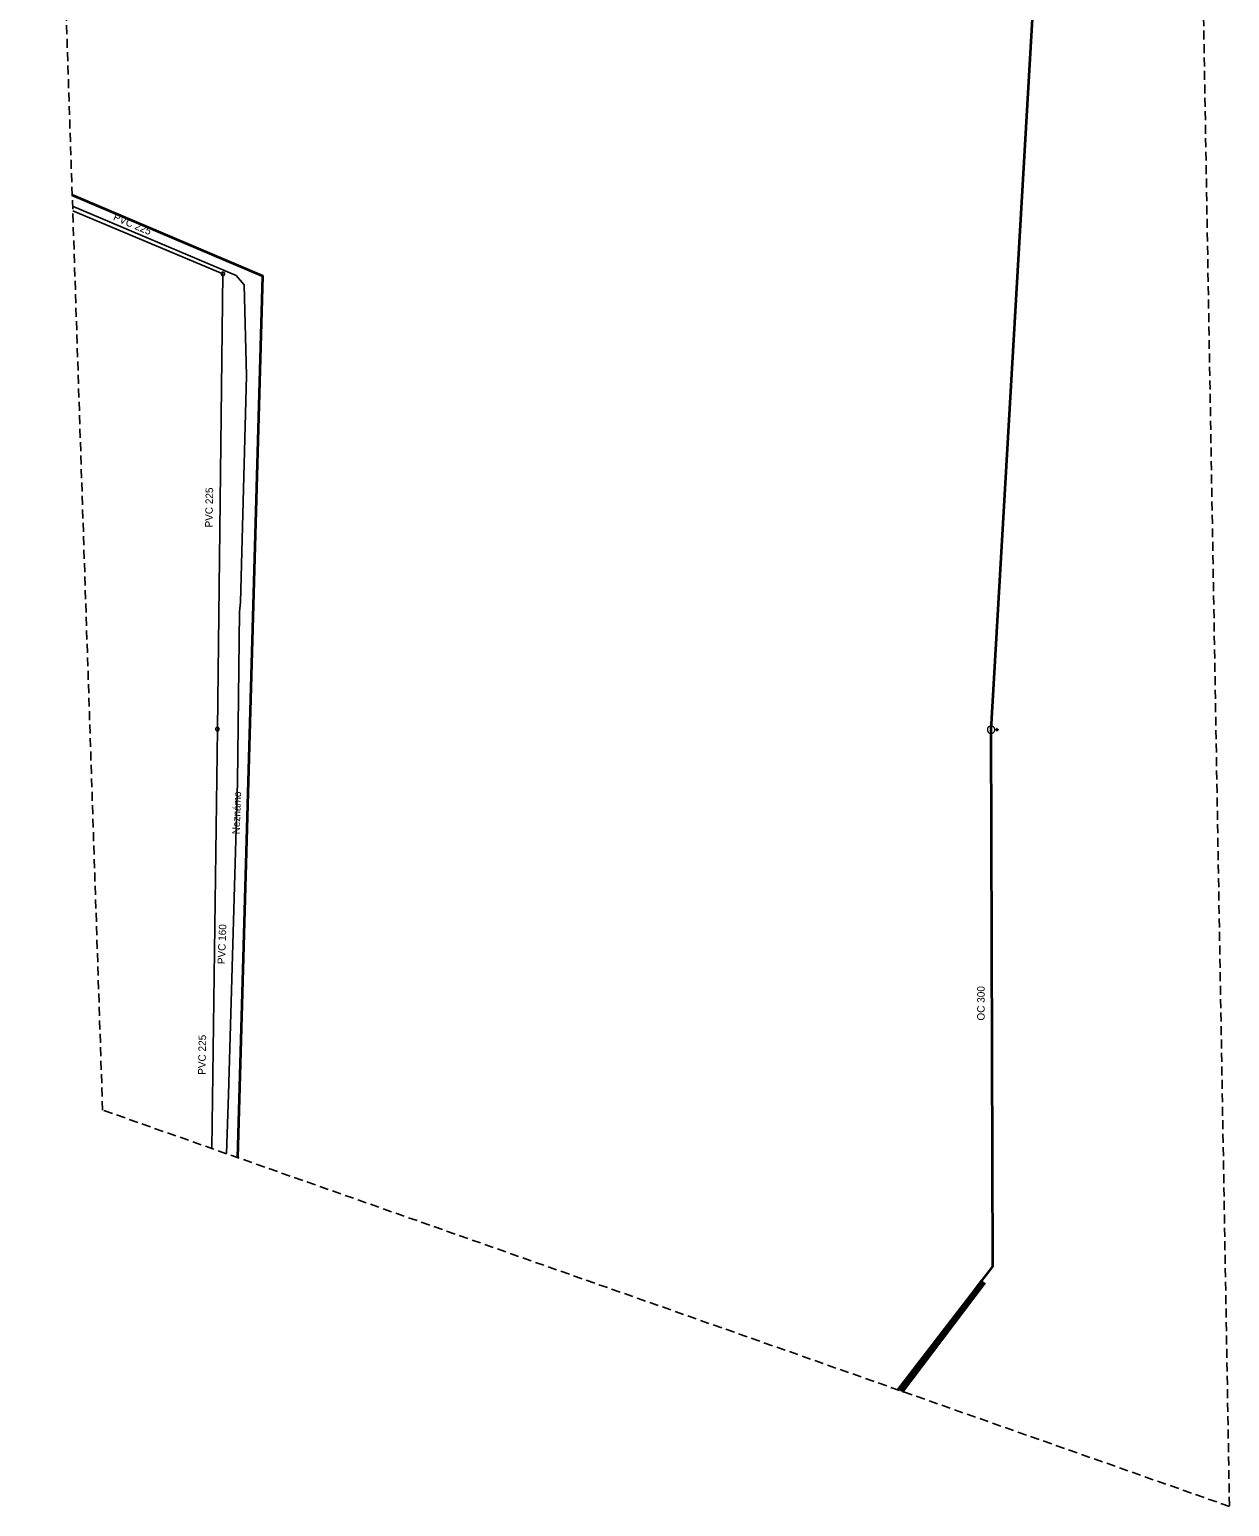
# Model space of a CAD drawing. Extents: x -724334 to -723692, y -972150 to -970648.
# Drawn here: x -723852.3 to -723691.8, y -972150.1 to -971952.5 of the extents above; entities that cross this region are included whole.
import ezdxf

# ---------------------------------------------------------------- set-up
doc = ezdxf.new("R2010")
doc.units = 0
doc.header["$LTSCALE"] = 0.4
doc.linetypes.add('MEDIUM_DASHED', pattern=[4.5, 3, -1.5])
for name, color, linetype, lineweight in [('1', 7, 'Continuous', 25), ('11', 7, 'Continuous', 13), ('17', 7, 'Continuous', 35), ('23', 7, 'Continuous', 13), ('3', 7, 'Continuous', 106)]:
    doc.layers.add(name, color=color, linetype=linetype, lineweight=lineweight)

msp = doc.modelspace()

# ---------------------------------------------------------------- linework, layer by layer
at = {"layer": '1', "linetype": 'MEDIUM_DASHED'}
msp.add_lwpolyline([(-723848.074, -970648.428), (-723714.095, -970720.999), (-724065.788, -971064.318), (-723792.249, -971201.088), (-723702.93, -971508.122), (-723691.766, -972150.101), (-723842.491, -972097.068), (-723864.821, -971424.385), (-723982.052, -971259.703), (-724333.745, -971117.352)], close=True, dxfattribs=at)
at = {"layer": '11', "lineweight": 35}
msp.add_lwpolyline([(-723824.393, -972103.436), (-723821.07, -971985.522), (-723846.553, -971974.691)], dxfattribs=at)
at = {"layer": '17', "lineweight": 25}
for p, q in [((-723846.484, -971976.784), (-723826.388, -971985.208)), ((-723826.388, -971985.208), (-723827.138, -972046.099)), ((-723827.138, -972046.099), (-723827.873, -972102.211))]:
    msp.add_line(p, q, dxfattribs=at)
at = {"layer": '17'}
msp.add_lwpolyline([(-723736.101, -972134.501), (-723723.419, -972117.993), (-723723.649, -972046.19), (-723706.064, -971743.847)], dxfattribs=at)
at = {"layer": '17', "lineweight": 25}
msp.add_lwpolyline([(-723846.505, -971976.143), (-723824.629, -971985.42), (-723823.55, -971986.68), (-723823.239, -971998.829), (-723824.05, -972029.1), (-723824.19, -972030.42), (-723824.44, -972053.219), (-723825.629, -972094.98), (-723825.929, -972102.895)], dxfattribs=at)
at = {"layer": '23'}
for p, q in [((-723826.345, -971984.959), (-723826.433, -971985.466)), ((-723827.095, -972045.85), (-723827.183, -972046.357)), ((-723722.692, -972046.18), (-723723.157, -972046.182)), ((-723722.94, -972046.017), (-723722.94, -972046.182)), ((-723722.938, -972046.347), (-723722.692, -972046.18)), ((-723722.917, -972046.031), (-723722.916, -972046.331)), ((-723722.889, -972046.048), (-723722.888, -972046.315)), ((-723722.866, -972046.066), (-723722.864, -972046.294)), ((-723722.843, -972046.083), (-723722.84, -972046.279)), ((-723722.818, -972046.098), (-723722.816, -972046.264)), ((-723722.791, -972046.114), (-723722.79, -972046.248)), ((-723722.767, -972046.13), (-723722.765, -972046.231)), ((-723722.743, -972046.149), (-723722.742, -972046.213)), ((-723722.716, -972046.164), (-723722.715, -972046.196))]:
    msp.add_line(p, q, dxfattribs=at)
for points in [[(-723826.14, -971985.253), (-723826.137, -971985.226), (-723826.136, -971985.2), (-723826.138, -971985.174), (-723826.143, -971985.149), (-723826.15, -971985.122), (-723826.161, -971985.098), (-723826.174, -971985.074), (-723826.188, -971985.054), (-723826.205, -971985.033), (-723826.225, -971985.016), (-723826.246, -971985), (-723826.268, -971984.986), (-723826.293, -971984.974), (-723826.318, -971984.967), (-723826.343, -971984.961), (-723826.369, -971984.958), (-723826.396, -971984.956), (-723826.422, -971984.958), (-723826.448, -971984.963), (-723826.473, -971984.97), (-723826.497, -971984.981), (-723826.52, -971984.994), (-723826.542, -971985.008), (-723826.561, -971985.026), (-723826.579, -971985.045), (-723826.596, -971985.067), (-723826.61, -971985.088), (-723826.621, -971985.113), (-723826.63, -971985.138), (-723826.635, -971985.163), (-723826.639, -971985.189), (-723826.64, -971985.215), (-723826.638, -971985.242), (-723826.632, -971985.268), (-723826.624, -971985.294), (-723826.614, -971985.317), (-723826.601, -971985.341), (-723826.588, -971985.362), (-723826.57, -971985.382), (-723826.549, -971985.399), (-723826.529, -971985.416), (-723826.506, -971985.43), (-723826.483, -971985.442), (-723826.458, -971985.45), (-723826.432, -971985.455), (-723826.407, -971985.459), (-723826.38, -971985.46), (-723826.354, -971985.458), (-723826.328, -971985.452), (-723826.302, -971985.445), (-723826.277, -971985.435), (-723826.254, -971985.422), (-723826.233, -971985.408), (-723826.213, -971985.39), (-723826.195, -971985.37), (-723826.179, -971985.349), (-723826.165, -971985.327), (-723826.155, -971985.302), (-723826.147, -971985.278)], [(-723826.89, -972046.144), (-723826.887, -972046.117), (-723826.886, -972046.091), (-723826.888, -972046.065), (-723826.893, -972046.04), (-723826.9, -972046.013), (-723826.911, -972045.989), (-723826.924, -972045.965), (-723826.938, -972045.945), (-723826.955, -972045.924), (-723826.975, -972045.907), (-723826.996, -972045.891), (-723827.018, -972045.877), (-723827.043, -972045.865), (-723827.068, -972045.858), (-723827.093, -972045.852), (-723827.119, -972045.849), (-723827.146, -972045.847), (-723827.172, -972045.849), (-723827.198, -972045.854), (-723827.223, -972045.861), (-723827.247, -972045.872), (-723827.27, -972045.885), (-723827.292, -972045.899), (-723827.311, -972045.917), (-723827.329, -972045.936), (-723827.346, -972045.958), (-723827.36, -972045.979), (-723827.371, -972046.004), (-723827.38, -972046.029), (-723827.385, -972046.054), (-723827.389, -972046.08), (-723827.39, -972046.106), (-723827.388, -972046.133), (-723827.382, -972046.159), (-723827.374, -972046.185), (-723827.364, -972046.208), (-723827.351, -972046.232), (-723827.338, -972046.253), (-723827.32, -972046.273), (-723827.299, -972046.29), (-723827.279, -972046.307), (-723827.256, -972046.321), (-723827.233, -972046.333), (-723827.208, -972046.341), (-723827.182, -972046.346), (-723827.157, -972046.35), (-723827.13, -972046.351), (-723827.104, -972046.349), (-723827.078, -972046.343), (-723827.052, -972046.336), (-723827.027, -972046.326), (-723827.004, -972046.313), (-723826.983, -972046.299), (-723826.963, -972046.281), (-723826.945, -972046.261), (-723826.929, -972046.24), (-723826.915, -972046.218), (-723826.905, -972046.193), (-723826.897, -972046.169)], [(-723723.645, -972046.69), (-723723.593, -972046.686), (-723723.542, -972046.679), (-723723.491, -972046.665), (-723723.442, -972046.646), (-723723.395, -972046.622), (-723723.352, -972046.592), (-723723.312, -972046.559), (-723723.274, -972046.522), (-723723.242, -972046.482), (-723723.214, -972046.438), (-723723.19, -972046.391), (-723723.173, -972046.34), (-723723.158, -972046.291), (-723723.15, -972046.238), (-723723.149, -972046.186), (-723723.153, -972046.135), (-723723.16, -972046.083), (-723723.174, -972046.032), (-723723.192, -972045.985), (-723723.216, -972045.938), (-723723.246, -972045.894), (-723723.279, -972045.853), (-723723.317, -972045.815), (-723723.357, -972045.784), (-723723.401, -972045.755), (-723723.448, -972045.731), (-723723.497, -972045.714), (-723723.547, -972045.701), (-723723.599, -972045.693), (-723723.652, -972045.69), (-723723.703, -972045.694), (-723723.755, -972045.701), (-723723.806, -972045.715), (-723723.854, -972045.734), (-723723.901, -972045.759), (-723723.945, -972045.787), (-723723.986, -972045.82), (-723724.022, -972045.857), (-723724.054, -972045.898), (-723724.083, -972045.942), (-723724.107, -972045.989), (-723724.125, -972046.038), (-723724.138, -972046.09), (-723724.146, -972046.142), (-723724.148, -972046.194), (-723724.144, -972046.246), (-723724.136, -972046.297), (-723724.123, -972046.348), (-723724.105, -972046.396), (-723724.08, -972046.443), (-723724.052, -972046.486), (-723724.018, -972046.525), (-723723.981, -972046.562), (-723723.94, -972046.597), (-723723.896, -972046.625), (-723723.849, -972046.649), (-723723.8, -972046.666), (-723723.749, -972046.679), (-723723.697, -972046.688)]]:
    msp.add_lwpolyline(points, close=True, dxfattribs=at)
msp.add_lwpolyline([(-723722.692, -972046.18), (-723722.94, -972046.017), (-723722.938, -972046.347)], dxfattribs=at)
at = {"layer": '3'}
msp.add_line((-723735.731, -972134.632), (-723724.649, -972119.993), dxfattribs=at)
at = {"layer": '3', "lineweight": 100}
msp.add_line((-723735.731, -972134.632), (-723724.649, -972119.993), dxfattribs=at)

# ---------------------------------------------------------------- texts
at = {"layer": '1'}
for s, rotation, p in [('PVC 225 ', 337, (-723841.15, -971977.951)), ('PVC 225 ', 89, (-723827.791, -972019.14)), ('Neznámo ', 88, (-723824.159, -972060.186)), ('PVC 160 ', 88, (-723826.118, -972077.569)), ('OC 300', 90, (-723724.509, -972085.094)), ('PVC 225 ', 89, (-723828.728, -972092.36))]:
    msp.add_text(s, height=1, rotation=rotation, dxfattribs=at).set_placement(p)

doc.saveas('drawing.dxf')
